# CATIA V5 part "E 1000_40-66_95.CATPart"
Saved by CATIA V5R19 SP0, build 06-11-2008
Definition: E 1000_40-66_95
Nomenclature: E 1000_40-66_95
Description: PART--DESC
Material "Steel": density 7860 kg/m3, Young's modulus 2e+11 Pa, Poisson ratio 0.266, thermal expansion 1.17e-05 1/K
Bounding box of the stored display mesh (mm): x 249.7 to 308.3, y -258.29 to -199.71, z -161 to 12
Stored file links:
  G:\UTB\Kombinované\Bakalářská práce\Catia\FORMA\E 1000_40-66_95.CATPart
  D:\Aplikace\CATIA\Nová složka\win_b64\startup\materials\Catalog.CATMaterial
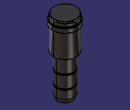
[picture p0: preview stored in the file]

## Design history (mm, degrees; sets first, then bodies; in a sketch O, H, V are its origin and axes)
Body1 "E 1000_40-66_95" (main body)
  Solid1: solid without history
